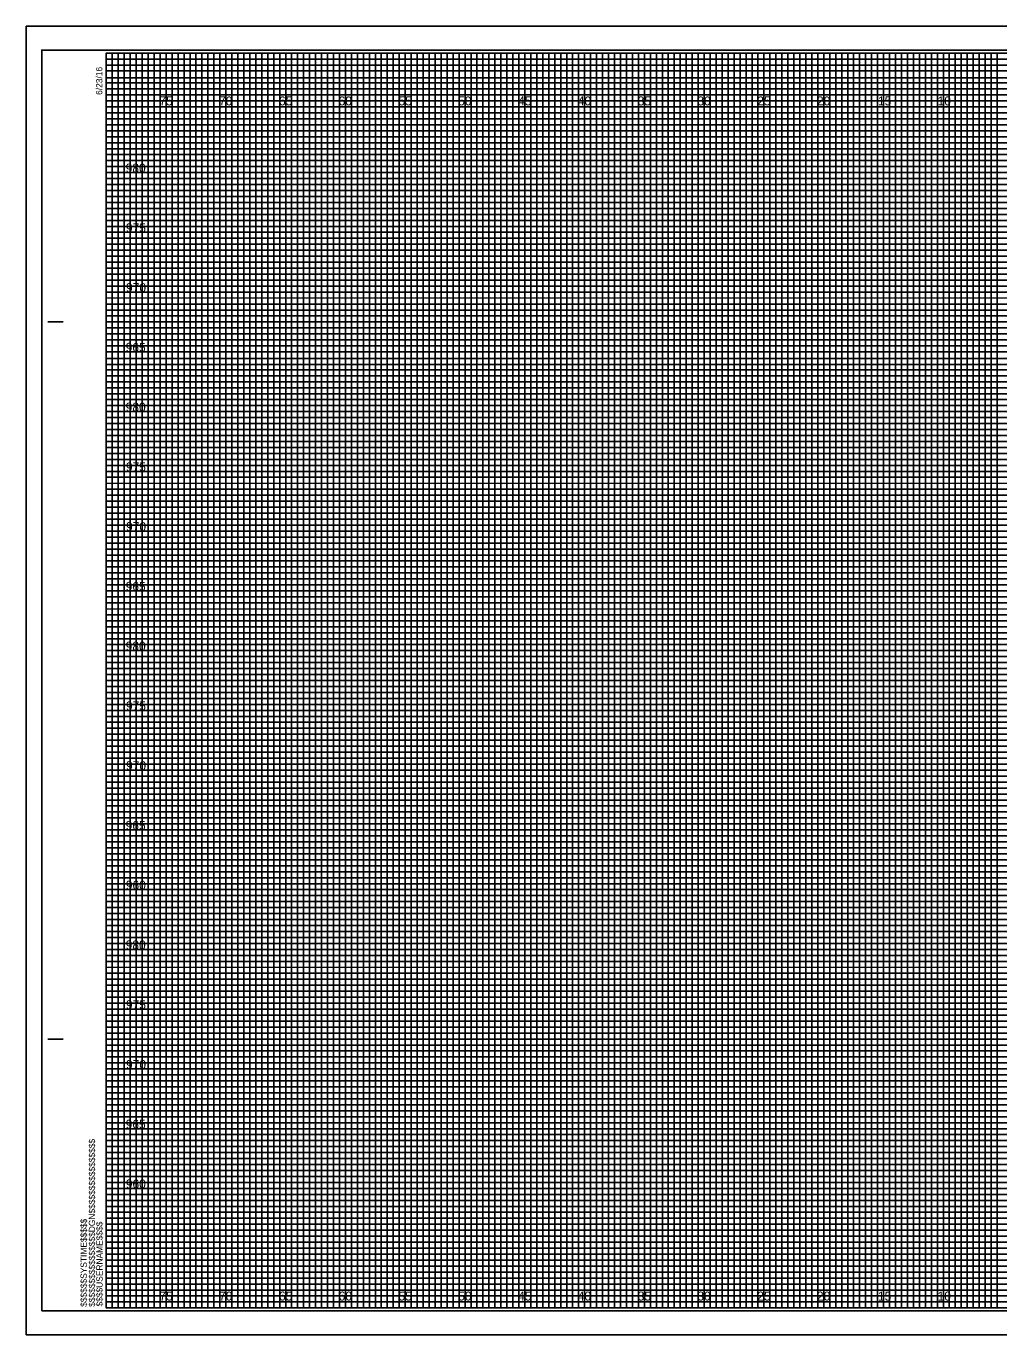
# Model space of a CAD drawing. Extents: x -7 to 162, y 328 to 437.
# Drawn here: x -6.7 to 74.6, y 327.7 to 437.2 of the extents above; entities that cross this region are included whole.
import ezdxf

# ---------------------------------------------------------------- set-up
doc = ezdxf.new("R2010")
doc.units = 0
for name, color, linetype in [('Prop XS Elevation Labels', 7, 'Continuous'), ('Prop XS Offset Labels', 7, 'Continuous'), ('Sheet Cross Section CELL', 7, 'Continuous'), ('Sheet Cross Section Grid Major CELL', 7, 'Continuous'), ('Sheet Cross Section Grid Middle CELL', 7, 'Continuous'), ('Sheet Cross Section Grid Minor 1 CELL', 7, 'Continuous'), ('Sheet Cross Section Grid Minor 2 CELL', 7, 'Continuous'), ('Sheet Cutting Line CELL', 7, 'Continuous'), ('Sheet DOT Grid CELL', 7, 'Continuous'), ('Sheet Plot Border Inside CELL', 7, 'Continuous'), ('Sheet Plot Border Outside CELL', 7, 'Continuous')]:
    doc.layers.add(name, color=color, linetype=linetype)

msp = doc.modelspace()

# ---------------------------------------------------------------- linework, layer by layer
at = {"layer": 'Sheet Cross Section CELL'}
for p, q in [((-4.9, 412.5), (-3.65, 412.5)), ((-4.85, 412.5), (-3.6, 412.5)), ((-4.9, 352.5), (-3.65, 352.5)), ((-4.85, 352.5), (-3.6, 352.5)), ((0, 330), (0, 330)), ((0, 330), (0, 330)), ((0, 330), (0, 330)), ((0, 330), (0, 330)), ((0, 330), (0, 330)), ((0, 330), (0, 330)), ((0, 330), (0, 330))]:
    msp.add_line(p, q, dxfattribs=at)
msp.add_lwpolyline([(160, 435), (0, 435), (0, 330), (160, 330)], close=True, dxfattribs=at)
at = {"layer": 'Sheet Cross Section Grid Major CELL'}
for p, q in [((5, 435), (0, 435)), ((5, 330), (5, 435)), ((15, 435), (10, 435)), ((10, 435), (10, 330)), ((15, 330), (15, 435)), ((25, 435), (20, 435)), ((20, 435), (20, 330)), ((25, 330), (25, 435)), ((35, 435), (30, 435)), ((30, 435), (30, 330)), ((35, 330), (35, 435)), ((45, 435), (40, 435)), ((40, 435), (40, 330)), ((45, 330), (45, 435)), ((55, 435), (50, 435)), ((50, 435), (50, 330)), ((55, 330), (55, 435)), ((65, 435), (60, 435)), ((60, 435), (60, 330)), ((65, 330), (65, 435)), ((75, 435), (70, 435)), ((70, 435), (70, 330)), ((10, 330), (5, 330)), ((20, 330), (15, 330)), ((30, 330), (25, 330)), ((40, 330), (35, 330)), ((50, 330), (45, 330)), ((60, 330), (55, 330)), ((70, 330), (65, 330))]:
    msp.add_line(p, q, dxfattribs=at)
for points in [[(0, 430), (160, 430), (160, 425), (0, 425)], [(0, 420), (160, 420), (160, 415), (0, 415)], [(0, 410), (160, 410), (160, 405), (0, 405)], [(0, 400), (160, 400), (160, 395), (0, 395)], [(0, 390), (160, 390), (160, 385), (0, 385)], [(0, 380), (160, 380), (160, 375), (0, 375)], [(0, 370), (160, 370), (160, 365), (0, 365)], [(0, 360), (160, 360), (160, 355), (0, 355)], [(0, 350), (160, 350), (160, 345), (0, 345)], [(0, 340), (160, 340), (160, 335), (0, 335)]]:
    msp.add_lwpolyline(points, dxfattribs=at)
at = {"layer": 'Sheet Cross Section Grid Middle CELL'}
for points in [[(0, 435), (2.5, 435), (2.5, 330), (7.5, 330), (7.5, 435), (12.5, 435), (12.5, 330), (17.5, 330), (17.5, 435), (22.5, 435), (22.5, 330), (27.5, 330), (27.5, 435), (32.5, 435), (32.5, 330), (37.5, 330), (37.5, 435), (42.5, 435), (42.5, 330), (47.5, 330), (47.5, 435), (52.5, 435), (52.5, 330), (57.5, 330), (57.5, 435), (62.5, 435), (62.5, 330), (67.5, 330), (67.5, 435), (72.5, 435), (72.5, 330), (77.5, 330)], [(0, 432.5), (137.5, 432.5)], [(0, 422.5), (160, 422.5), (160, 427.5), (0, 427.5)], [(0, 412.5), (160, 412.5), (160, 417.5), (0, 417.5)], [(0, 402.5), (160, 402.5), (160, 407.5), (0, 407.5)], [(0, 392.5), (160, 392.5), (160, 397.5), (0, 397.5)], [(0, 382.5), (160, 382.5), (160, 387.5), (0, 387.5)], [(0, 372.5), (160, 372.5), (160, 377.5), (0, 377.5)], [(0, 362.5), (160, 362.5), (160, 367.5), (0, 367.5)], [(0, 352.5), (160, 352.5), (160, 357.5), (0, 357.5)], [(0, 342.5), (160, 342.5), (160, 347.5), (0, 347.5)], [(0, 332.5), (160, 332.5), (160, 337.5), (0, 337.5)]]:
    msp.add_lwpolyline(points, dxfattribs=at)
at = {"layer": 'Sheet Cross Section Grid Minor 1 CELL'}
for p, q in [((0, 434.5), (130, 434.5)), ((130, 433.99), (0, 433.99)), ((0, 433.99), (0, 433.5)), ((0, 433.5), (130, 433.5)), ((130, 432.94), (0, 432.94)), ((0, 432.94), (0, 432)), ((0, 432), (160, 432))]:
    msp.add_line(p, q, dxfattribs=at)
for points in [[(0, 431.5), (135, 431.5), (160, 431.5), (160, 431), (0, 431)], [(0, 430.5), (160, 430.5), (160, 429.5), (0, 429.5)], [(0, 429), (160, 429), (160, 428.5), (0, 428.49)], [(0, 428), (160, 428), (160, 427), (0, 427)], [(0, 426.5), (160, 426.5), (160, 426), (0, 426)], [(0, 425.5), (160, 425.5), (160, 424.5), (0, 424.5)], [(0, 424), (160, 424), (160, 423.5), (0, 423.5)], [(0, 423), (160, 423), (160, 422), (0, 422)], [(0, 421.5), (160, 421.5), (160, 421), (0, 421)], [(0, 420.5), (160, 420.5), (160, 419.5), (0, 419.5)], [(0, 419), (160, 419), (160, 418.5), (0, 418.5)], [(0, 418), (160, 418), (160, 416.98), (160, 416.5), (160, 416), (0, 416)], [(0, 417), (160, 417), (160, 416.5), (0, 416.5)], [(0, 415.5), (160, 415.5), (160, 414.5), (0, 414.51)], [(0, 414.51), (160, 414.5), (160, 414), (0, 414)], [(0, 413.5), (160, 413.5), (160, 413), (0, 413)], [(0, 412), (160, 412), (160, 411.5), (0, 411.5)], [(0, 411), (160, 411), (160, 410.5), (0, 410.5)], [(-0.04, 409.44), (160, 409.44), (160, 408.94), (-0.04, 408.94)], [(0, 408.5), (160, 408.5), (160, 408), (0, 408)], [(0, 407), (160, 407), (160, 406.5), (0, 406.5)], [(0, 406), (160, 406), (160, 405.5), (0, 405.5)], [(0, 404.5), (160, 404.5), (160, 404), (0, 404)], [(0, 403.5), (160, 403.5), (160, 403), (0, 403)], [(0, 402), (160, 402), (160, 401.5), (0, 401.5)], [(0, 401), (160, 401), (160, 400.5), (0, 400.5)], [(0, 399.5), (160, 399.5), (160, 398.99), (0, 399)], [(0, 398.5), (160, 398.5), (160, 398), (0, 398)], [(0, 397), (160, 397), (160, 396.5), (0, 396.5)], [(0, 396), (160, 396), (160, 395.5), (0, 395.5)], [(0, 394.5), (160, 394.5), (160, 394), (0, 394)], [(0, 393.5), (160, 393.5), (160, 393), (0, 393)], [(0, 392), (160, 392), (160, 391.5), (0, 391.5)], [(0, 391), (160, 391), (160, 390.5), (0, 390.5)], [(0, 389.5), (160, 389.5), (160, 389), (0, 389)], [(0, 388.5), (160.03, 388.45), (160, 388), (0, 388)], [(0, 387), (160, 387), (160, 386.5), (0, 386.5)], [(0, 386), (160, 386), (160, 385.5), (0, 385.5)], [(0, 384.5), (160, 384.5), (160, 384), (0, 384)], [(0, 383.5), (160, 383.5), (160, 383), (0, 383)], [(0, 382), (160, 382), (160, 381.5), (0, 381.5)], [(0, 381), (160, 381), (160, 380.5), (0, 380.5)], [(0, 379.5), (160, 379.5), (160, 379), (0, 379)], [(0, 378.5), (160, 378.5), (160, 378), (0, 378)], [(0, 377), (160, 377), (160, 376.5), (0, 376.5)], [(0, 376), (160, 376), (160, 375.5), (0, 375.5)], [(0, 374.5), (160, 374.5), (160, 374), (0, 374)], [(0, 373.5), (160, 373.5), (160, 373), (0, 373)], [(0, 372), (160, 372), (160, 371.5), (0, 371.5)], [(0, 371), (160, 371), (160, 370.5), (0, 370.5)], [(0, 369.5), (160, 369.5), (160, 368.99), (0, 369)], [(0, 368.5), (160, 368.5), (160, 368), (0, 368)], [(0, 367), (160, 367), (160, 366.5), (0, 366.5)], [(0, 366), (160, 366), (160, 365.5), (0, 365.5)], [(0, 364.5), (160, 364.5), (160, 364), (0, 364)], [(0, 363.5), (160, 363.5), (160, 363), (0, 363)], [(0, 362), (160, 362), (160, 361.5), (0, 361.5)], [(0, 361), (160, 361), (160, 360.5), (0, 360.5)], [(0, 359.5), (160, 359.5), (160, 359), (0, 359)], [(0, 358.5), (160.03, 358.45), (160, 358), (0, 358)], [(0, 357), (160, 357), (160, 356.5), (0, 356.5)], [(0, 356), (160, 356), (160, 355.5), (0, 355.5)], [(0, 354.5), (160, 354.5), (160, 354), (0, 354)], [(0, 353.5), (160, 353.5), (160, 353), (0, 353)], [(0, 352), (160, 352), (160, 351.5), (0, 351.5)], [(0, 351), (160, 351), (160, 350.5), (0, 350.5)], [(0, 349.5), (160, 349.5), (160, 349), (0, 349)], [(0, 348.5), (160, 348.5), (160, 348), (0, 348)], [(0, 347), (160, 347), (160, 346.5), (0, 346.5)], [(0, 346), (160, 346), (160, 345.5), (0, 345.5)], [(0, 344.5), (160, 344.5), (160, 344), (0, 344)], [(0, 343.5), (160, 343.5), (160, 343), (0, 343)], [(0, 342), (160, 342), (160, 341.5), (0, 341.5)], [(0, 341), (160, 341), (160, 340.5), (0, 340.5)], [(0, 339.5), (160, 339.5), (160, 339), (0, 339)], [(0, 338.5), (160, 338.5), (160, 338), (0, 338)], [(0, 337), (160, 337), (160, 336.5), (0, 336.5)], [(0, 336), (160, 336), (160, 335.5), (0, 335.5)], [(0, 334.5), (160, 334.5), (160, 334), (0, 334)], [(0, 333.5), (160, 333.5), (160, 333), (0, 333)], [(0, 332), (160, 332), (160, 331.5), (0, 331.5)], [(0, 331), (160, 331), (160, 330.5), (0, 330.5)]]:
    msp.add_lwpolyline(points, dxfattribs=at)
at = {"layer": 'Sheet Cross Section Grid Minor 2 CELL'}
for points in [[(0, 330), (0.5, 330), (0.5, 435), (1, 435), (1, 330)], [(1, 330), (1.5, 330), (1.5, 435), (2, 435), (2, 330)], [(2.5, 330), (3, 330), (3, 435), (3.5, 435), (3.5, 330)], [(3.5, 330), (4, 330), (4, 435), (4.5, 435), (4.5, 330)], [(5, 330), (5.5, 330), (5.5, 435), (6, 435), (6, 330)], [(6, 330), (6.5, 330), (6.5, 435), (7, 435), (7, 330)], [(7.5, 330), (8, 330), (8, 435), (8.5, 435), (8.5, 330)], [(8.5, 330), (9, 330), (9, 435), (9.5, 435), (9.5, 330)], [(10, 330), (10.5, 330), (10.5, 435), (11, 435), (11, 330)], [(11, 330), (11.5, 330), (11.5, 435), (12, 435), (12, 330)], [(12.5, 330), (13, 330), (13, 435), (13.5, 435), (13.5, 330)], [(13.5, 330), (14, 330), (14, 435), (14.5, 435), (14.5, 330)], [(15, 330), (15.5, 330), (15.5, 435), (16, 435), (16, 330)], [(16, 330), (16.5, 330), (16.5, 435), (17, 435), (17, 330)], [(17.5, 330), (18, 330), (18, 435), (18.5, 435), (18.5, 330)], [(18.5, 330), (19, 330), (19, 435), (19.5, 435), (19.5, 330)], [(20, 330), (20.5, 330), (20.5, 435), (21, 435), (21, 330)], [(21, 330), (21.5, 330), (21.5, 435), (22, 435), (22, 330)], [(22.5, 330), (23, 330), (23, 435), (23.5, 435), (23.5, 330)], [(23.5, 330), (24, 330), (24, 435), (24.5, 435), (24.5, 330)], [(25, 330), (25.5, 330), (25.5, 435), (26, 435), (26, 330)], [(26, 330), (26.5, 330), (26.5, 435), (27, 435), (27, 330)], [(27.5, 330), (28, 330), (28, 435), (28.5, 435), (28.5, 330)], [(28.5, 330), (29, 330), (29, 435), (29.5, 435), (29.5, 330)], [(30, 330), (30.5, 330), (30.5, 435), (31, 435), (31, 330)], [(31, 330), (31.5, 330), (31.5, 435), (32, 435), (32, 330)], [(32.5, 330), (33, 330), (33, 435), (33.5, 435), (33.5, 330)], [(33.5, 330), (34, 330), (34, 435), (34.5, 435), (34.5, 330)], [(35, 330), (35.5, 330), (35.5, 435), (36, 435), (36, 330)], [(36, 330), (36.5, 330), (36.5, 435), (37, 435), (37, 330)], [(37.5, 330), (38, 330), (38, 435), (38.5, 435), (38.5, 330)], [(38.5, 330), (39, 330), (39, 435), (39.5, 435), (39.5, 330)], [(40, 330), (40.5, 330), (40.5, 435), (41, 435), (41, 330)], [(41, 330), (41.5, 330), (41.5, 435), (42, 435), (42, 330)], [(42.5, 330), (43, 330), (43, 435), (43.5, 435), (43.5, 330)], [(43.5, 330), (44, 330), (44, 435), (44.5, 435), (44.5, 330)], [(45, 330), (45.5, 330), (45.5, 435), (46, 435), (46, 330)], [(46, 330), (46.5, 330), (46.5, 435), (47, 435), (47, 330)], [(47.5, 330), (48, 330), (48, 435), (48.5, 435), (48.5, 330)], [(48.5, 330), (49, 330), (49, 435), (49.5, 435), (49.5, 330)], [(50, 330), (50.5, 330), (50.5, 435), (51, 435), (51, 330)], [(51, 330), (51.5, 330), (51.5, 435), (52, 435), (52, 330)], [(52.5, 330), (53, 330), (53, 435), (53.5, 435), (53.5, 330)], [(53.5, 330), (54, 330), (54, 435), (54.5, 435), (54.5, 330)], [(55, 330), (55.5, 330), (55.5, 435), (56, 435), (56, 330)], [(56, 330), (56.5, 330), (56.5, 435), (57, 435), (57, 330)], [(57.5, 330), (58, 330), (58, 435), (58.5, 435), (58.5, 330)], [(58.5, 330), (59, 330), (59, 435), (59.5, 435), (59.5, 330)], [(60, 330), (60.5, 330), (60.5, 435), (61, 435), (61, 330)], [(61, 330), (61.5, 330), (61.5, 435), (62, 435), (62, 330)], [(62.5, 330), (63, 330), (63, 435), (63.5, 435), (63.5, 330)], [(63.5, 330), (64, 330), (64, 435), (64.5, 435), (64.5, 330)], [(65, 330), (65.5, 330), (65.5, 435), (66, 435), (66, 330)], [(66, 330), (66.5, 330), (66.5, 435), (67, 435), (67, 330)], [(67.5, 330), (68, 330), (68, 435), (68.5, 435), (68.5, 330)], [(68.5, 330), (69, 330), (69, 435), (69.5, 435), (69.5, 330)], [(70, 330), (70.5, 330), (70.5, 435), (71, 435), (71, 330)], [(71, 330), (71.5, 330), (71.5, 435), (72, 435), (72, 330)], [(72.5, 330), (73, 330), (73, 435), (73.5, 435), (73.5, 330)], [(73.5, 330), (74, 330), (74, 435), (74.5, 435), (74.5, 330)]]:
    msp.add_lwpolyline(points, dxfattribs=at)
at = {"layer": 'Sheet Cutting Line CELL'}
for p, q in [((161.65, 437.25), (-6.7, 437.25)), ((-6.7, 437.25), (-6.7, 327.75)), ((-6.7, 327.75), (161.65, 327.75))]:
    msp.add_line(p, q, dxfattribs=at)
at = {"layer": 'Sheet DOT Grid CELL'}
for p, q in [((5, 330), (5, 435)), ((10, 330), (10, 435)), ((15, 330), (15, 435)), ((20, 330), (20, 435)), ((25, 330), (25, 435)), ((30, 330), (30, 435)), ((35, 330), (35, 435)), ((40, 330), (40, 435)), ((45, 330), (45, 435)), ((50, 330), (50, 435)), ((55, 330), (55, 435)), ((60, 330), (60, 435)), ((65, 330), (65, 435)), ((70, 330), (70, 435)), ((0, 430), (160, 430)), ((0, 425), (160, 425)), ((0, 420), (160, 420)), ((0, 415), (160, 415)), ((0, 410), (160, 410)), ((0, 405), (160, 405)), ((0, 400), (160, 400)), ((0, 395), (160, 395)), ((0, 390), (160, 390)), ((0, 385), (160, 385)), ((0, 380), (160, 380)), ((0, 375), (160, 375)), ((0, 370), (160, 370)), ((0, 365), (160, 365)), ((0, 360), (160, 360)), ((0, 355), (160, 355)), ((0, 350), (160, 350)), ((0, 345), (160, 345)), ((0, 340), (160, 340)), ((0, 335), (160, 335))]:
    msp.add_line(p, q, dxfattribs=at)
at = {"layer": 'Sheet Plot Border Inside CELL'}
msp.add_lwpolyline([(-5.4, 329.75), (161.2, 329.75), (161.2, 435.25), (-5.4, 435.25)], close=True, dxfattribs=at)
at = {"layer": 'Sheet Plot Border Outside CELL'}
msp.add_lwpolyline([(-6.7, 327.75), (161.65, 327.75), (161.65, 437.25), (-6.7, 437.25)], close=True, dxfattribs=at)

# ---------------------------------------------------------------- texts
at = {"layer": 'Prop XS Elevation Labels'}
for s, p in [('980', (1.62, 425)), ('975', (1.64, 420)), ('970', (1.65, 415)), ('965', (1.62, 410)), ('980', (1.62, 405)), ('975', (1.64, 400)), ('970', (1.65, 395)), ('965', (1.62, 390)), ('980', (1.62, 385)), ('975', (1.64, 380)), ('970', (1.65, 375)), ('965', (1.62, 370)), ('960', (1.63, 365)), ('980', (1.62, 360)), ('975', (1.64, 355)), ('970', (1.65, 350)), ('965', (1.62, 345)), ('960', (1.63, 340))]:
    msp.add_text(s, height=0.75, dxfattribs=at).set_placement(p)
at = {"layer": 'Prop XS Offset Labels'}
for s, p in [('75', (4.44, 430.62)), ('70', (9.43, 430.62)), ('65', (14.44, 430.62)), ('60', (19.43, 430.62)), ('55', (24.44, 430.62)), ('50', (29.43, 430.62)), ('45', (34.44, 430.62)), ('40', (39.43, 430.62)), ('35', (44.44, 430.62)), ('30', (49.43, 430.62)), ('25', (54.44, 430.62)), ('20', (59.43, 430.62)), ('15', (64.53, 430.62)), ('10', (69.52, 430.62)), ('75', (4.44, 330.62)), ('70', (9.43, 330.62)), ('65', (14.44, 330.62)), ('60', (19.43, 330.62)), ('55', (24.44, 330.62)), ('50', (29.43, 330.62)), ('45', (34.44, 330.62)), ('40', (39.43, 330.62)), ('35', (44.44, 330.62)), ('30', (49.43, 330.62)), ('25', (54.44, 330.62)), ('20', (59.43, 330.62)), ('15', (64.53, 330.62)), ('10', (69.52, 330.62))]:
    msp.add_text(s, height=0.75, dxfattribs=at).set_placement(p)
at = {"layer": 'Sheet Cross Section CELL'}
for s, p in [('6/23/16', (-0.33, 431.5)), ('$$$$$$$$$$$$$$$$DGN$$$$$$$$$$$$$$$$', (-0.94, 330.09)), ('$$$$$$SYSTIME$$$$$', (-1.63, 330.09)), ('$$$$USERNAME$$$$', (-0.31, 330.12))]:
    msp.add_text(s, height=0.525, rotation=90, dxfattribs=at).set_placement(p)

doc.saveas('drawing.dxf')
